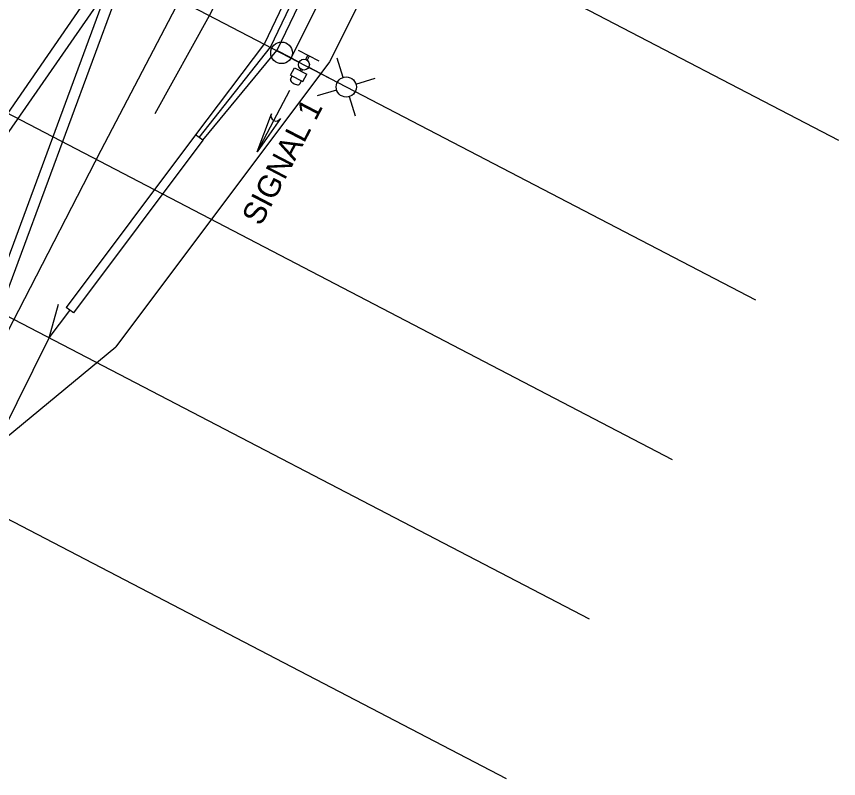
# Model space of a CAD drawing. Extents: x 2034057 to 2035954, y 247386 to 249135.
# Drawn here: x 2034166.1 to 2034280.3, y 247621.4 to 247727.3 of the extents above; entities that cross this region are included whole.
import ezdxf

# ---------------------------------------------------------------- set-up
doc = ezdxf.new("R2010")
doc.units = 0
for name, color, linetype in [('Default', 7, 'Continuous'), ('DR_X_Storm_Sewer', 7, 'Continuous'), ('DR_X_Text', 7, 'Continuous'), ('DV_X_Text', 7, 'Continuous'), ('PV_X_Driveway', 7, 'Continuous'), ('RD_X_GR_Lt', 7, 'Continuous'), ('RD_X_GR_Rt', 7, 'Continuous'), ('RS_Raster1', 7, 'Continuous'), ('SC_Scratch1', 7, 'Continuous'), ('SV_X_Break_Lines', 7, 'Continuous'), ('XS_X_Ground_Line', 7, 'Continuous')]:
    doc.layers.add(name, color=color, linetype=linetype)

msp = doc.modelspace()

# ---------------------------------------------------------------- linework, layer by layer
at = {"layer": 'Default'}
for p, q in [((2034102.89, 247802.48), (2034280.28, 247710.12)), ((2034091.34, 247780.31), (2034268.74, 247687.94)), ((2034079.8, 247758.13), (2034257.19, 247665.77)), ((2034068.25, 247735.96), (2034245.65, 247643.6)), ((2034056.71, 247713.78), (2034234.1, 247621.42))]:
    msp.add_line(p, q, dxfattribs=at)
at = {"layer": 'DR_X_Storm_Sewer'}
for p, q in [((2034200.52, 247723.55), (2034190.96, 247710.86)), ((2034191.96, 247710.11), (2034202.26, 247722.56)), ((2034204.23, 247721.53), (2034202.26, 247722.56))]:
    msp.add_line(p, q, dxfattribs=at)
for points in [[(2034256.26, 247823.15), (2034236.29, 247789.47), (2034223.22, 247768.07), (2034211.27, 247746.04), (2034200.52, 247723.55), (2034200.47, 247723.49)], [(2034257.98, 247822.13), (2034238, 247788.44), (2034224.95, 247767.07), (2034213.06, 247745.13), (2034202.26, 247722.56)], [(2034204.23, 247721.53), (2034215.42, 247743.89), (2034228.62, 247765.2)]]:
    msp.add_lwpolyline(points, dxfattribs=at)
at = {"layer": 'DR_X_Text'}
for points in [[(2034185.35, 247713.83), (2034192.91, 247727.42), (2034204.24, 247749.71), (2034212.91, 247766.55)], [(2034159.51, 247660.26), (2034170.62, 247682.66), (2034171.93, 247687.34)]]:
    msp.add_lwpolyline(points, dxfattribs=at)
at = {"layer": 'DV_X_Text'}
for p, q in [((2034190.96, 247710.86), (2034172.98, 247686.85)), ((2034191.96, 247710.11), (2034190.96, 247710.86)), ((2034191.96, 247710.11), (2034173.98, 247686.1)), ((2034173.98, 247686.1), (2034172.98, 247686.85))]:
    msp.add_line(p, q, dxfattribs=at)
at = {"layer": 'PV_X_Driveway'}
msp.add_line((2034191.69, 247761.92), (2034157.41, 247669.23), dxfattribs=at)
at = {"layer": 'RD_X_GR_Lt'}
msp.add_line((2034204.76, 247768.61), (2034133.48, 247665.92), dxfattribs=at)
msp.add_lwpolyline([(2034188.71, 247729.61), (2034177.8, 247708.67), (2034166.36, 247686.43), (2034157.41, 247669.23)], dxfattribs=at)
at = {"layer": 'RD_X_GR_Rt'}
for p, q in [((2034205.22, 247722.6), (2034208.09, 247721.11)), ((2034206.55, 247721.91), (2034206.25, 247721.32)), ((2034206.55, 247721.91), (2034206.25, 247721.32)), ((2034206.76, 247721.8), (2034206.46, 247721.21)), ((2034206.76, 247721.8), (2034206.46, 247721.21)), ((2034204.22, 247721.54), (2034205.34, 247720.95)), ((2034211.48, 247718.83), (2034210.65, 247721.51)), ((2034204.15, 247719.14), (2034204.68, 247720.15)), ((2034204.68, 247720.15), (2034206.4, 247719.26)), ((2034205.56, 247720), (2034205.44, 247719.76)), ((2034205.56, 247720), (2034205.44, 247719.76)), ((2034205.77, 247719.89), (2034205.65, 247719.65)), ((2034205.77, 247719.89), (2034205.65, 247719.65)), ((2034206.68, 247720.25), (2034210.65, 247718.15)), ((2034204.15, 247719.14), (2034205.88, 247718.24)), ((2034204.15, 247718.59), (2034204.37, 247719.02)), ((2034204.15, 247718.59), (2034204.37, 247719.02)), ((2034205.43, 247717.92), (2034205.65, 247718.35)), ((2034205.43, 247717.92), (2034205.65, 247718.35)), ((2034205.88, 247718.24), (2034206.4, 247719.26)), ((2034213.22, 247717.91), (2034215.9, 247718.73)), ((2034203.99, 247717.03), (2034199.53, 247708.47)), ((2034210.55, 247717.08), (2034207.87, 247716.26)), ((2034212.3, 247716.16), (2034213.13, 247713.48)), ((2034199.53, 247708.47), (2034201.5, 247713.78)), ((2034202.75, 247713.13), (2034199.53, 247708.47))]:
    msp.add_line(p, q, dxfattribs=at)
for centre, radius in [((2034202.9, 247722.24), 1.5), ((2034206.01, 247720.61), 0.757), ((2034211.89, 247717.5), 1.4)]:
    msp.add_circle(centre, radius, dxfattribs=at)
msp.add_arc((2034202.13, 247713.46), 0.703, 152.4894, 332.4894, dxfattribs=at)
msp.add_ellipse((2034204.79, 247718.25), major_axis=(-0.64, 0.332), ratio=0.45371, start_param=0, end_param=3.141593, dxfattribs=at)
msp.add_ellipse((2034204.79, 247718.25), major_axis=(-0.64, 0.332), ratio=0.45371, start_param=0, end_param=3.141593, dxfattribs=at)
at = {"layer": 'RS_Raster1'}
msp.add_line((2034151.87, 247658.6), (2034196.67, 247779.59), dxfattribs=at)
at = {"layer": 'SC_Scratch1'}
msp.add_line((2034138.55, 247675.74), (2034192.77, 247754.24), dxfattribs=at)
at = {"layer": 'SV_X_Break_Lines'}
msp.add_line((2034170.62, 247682.66), (2034173.48, 247686.47), dxfattribs=at)
msp.add_lwpolyline([(2034191.46, 247710.48), (2034201.37, 247723.02), (2034212.16, 247745.59), (2034224.08, 247767.57), (2034237.15, 247788.95), (2034257.12, 247822.64)], dxfattribs=at)
msp.add_lwpolyline([(2034203.45, 247726.48), (2034203.45, 247726.48), (2034203.45, 247726.48)], close=True, dxfattribs=at)
at = {"layer": 'XS_X_Ground_Line'}
msp.add_line((2034209.54, 247720.98), (2034179.88, 247681.38), dxfattribs=at)
for points in [[(2034232.88, 247762.57), (2034219.79, 247741.45), (2034209.54, 247720.98)], [(2034133.48, 247673.81), (2034156.29, 247661.93), (2034179.88, 247681.38)]]:
    msp.add_lwpolyline(points, dxfattribs=at)

# ---------------------------------------------------------------- texts
at = {"layer": 'RD_X_GR_Rt'}
msp.add_text('SIGNAL 1', height=3.125, rotation=62.4894, dxfattribs=at).set_placement((2034200.01, 247698.06))

doc.saveas('drawing.dxf')
